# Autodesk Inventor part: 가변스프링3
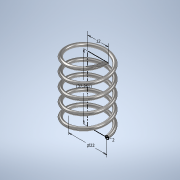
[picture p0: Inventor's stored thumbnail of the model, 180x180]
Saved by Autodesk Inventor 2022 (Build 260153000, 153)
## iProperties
Created: 2021-07
Part Number: 가변스프링3
Material: 강철, 연강
Document SubType Name: Modeling
Designer: micke
Density: 7.85 g/cm^3
Appearance: 반연마
Mass: 8.42401 g
Surface Area: 21.7265 cm^2
Volume: 1.07312 cm^3
Author: micke
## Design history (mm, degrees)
sketch "스케치1"
  geometry: L1 (0, 0)-(0, 37.261); L2 (0, 37.261)-(12, 37.261); L3 (0, 0)-(11, 0); C1 r 1 at (11, 0)
  constraints: 6 end point, 2 horizontal, 1 centre point, 1 coincident, 1 vertical
  dimensions: "d0" = 37.2612 distance of L1.start L1.end (derived); "d1" = 2 diameter of C1; "d2" = 22 diameter of L3.end L1; "d3" = 12 distance of L1.end L2.end
feature "코일1" sketch "스케치1" pitch "d4" = 10; turns "d6" = 5; dims "d5" = 37.2612 (= d0), "d7" = 0, angle "d8" = 90 deg, angle "d9" = 90 deg, "d10" = 0, "d11" = 0
sketch "스케치2"
  geometry: L1 (37.261, 12.5)-(0, 12.5); L2 (0, 12.5)-(0, -12.5); L3 (0, -12.5)-(37.261, -12.5); L4 (37.261, -12.5)-(37.261, 12.5); 2 further points
  constraints: 8 end point, 2 parallel, 1 coincident, 1 horizontal, 1 midpoint, 1 perpendicular
  dimensions: "d12" = 37.2612 distance of L1.start L1.end (= d0); "d13" = 25 distance of L3.end L1.start
extrude "돌출1" sketch "스케치2" extent not by distance; stored distance "d14" = 0; taper "d15" = 0 deg
node "솔리드1"
feature "A9D066F2-1C7D-4E18-AEED-F7BC21143FA4" dims "d4" = 10, "d5" = 37.2612 (= d0), "d6" = 50, "d7" = 0, "d8" = 90 deg, "d9" = 90 deg, "d10" = 0, "d11" = 0
